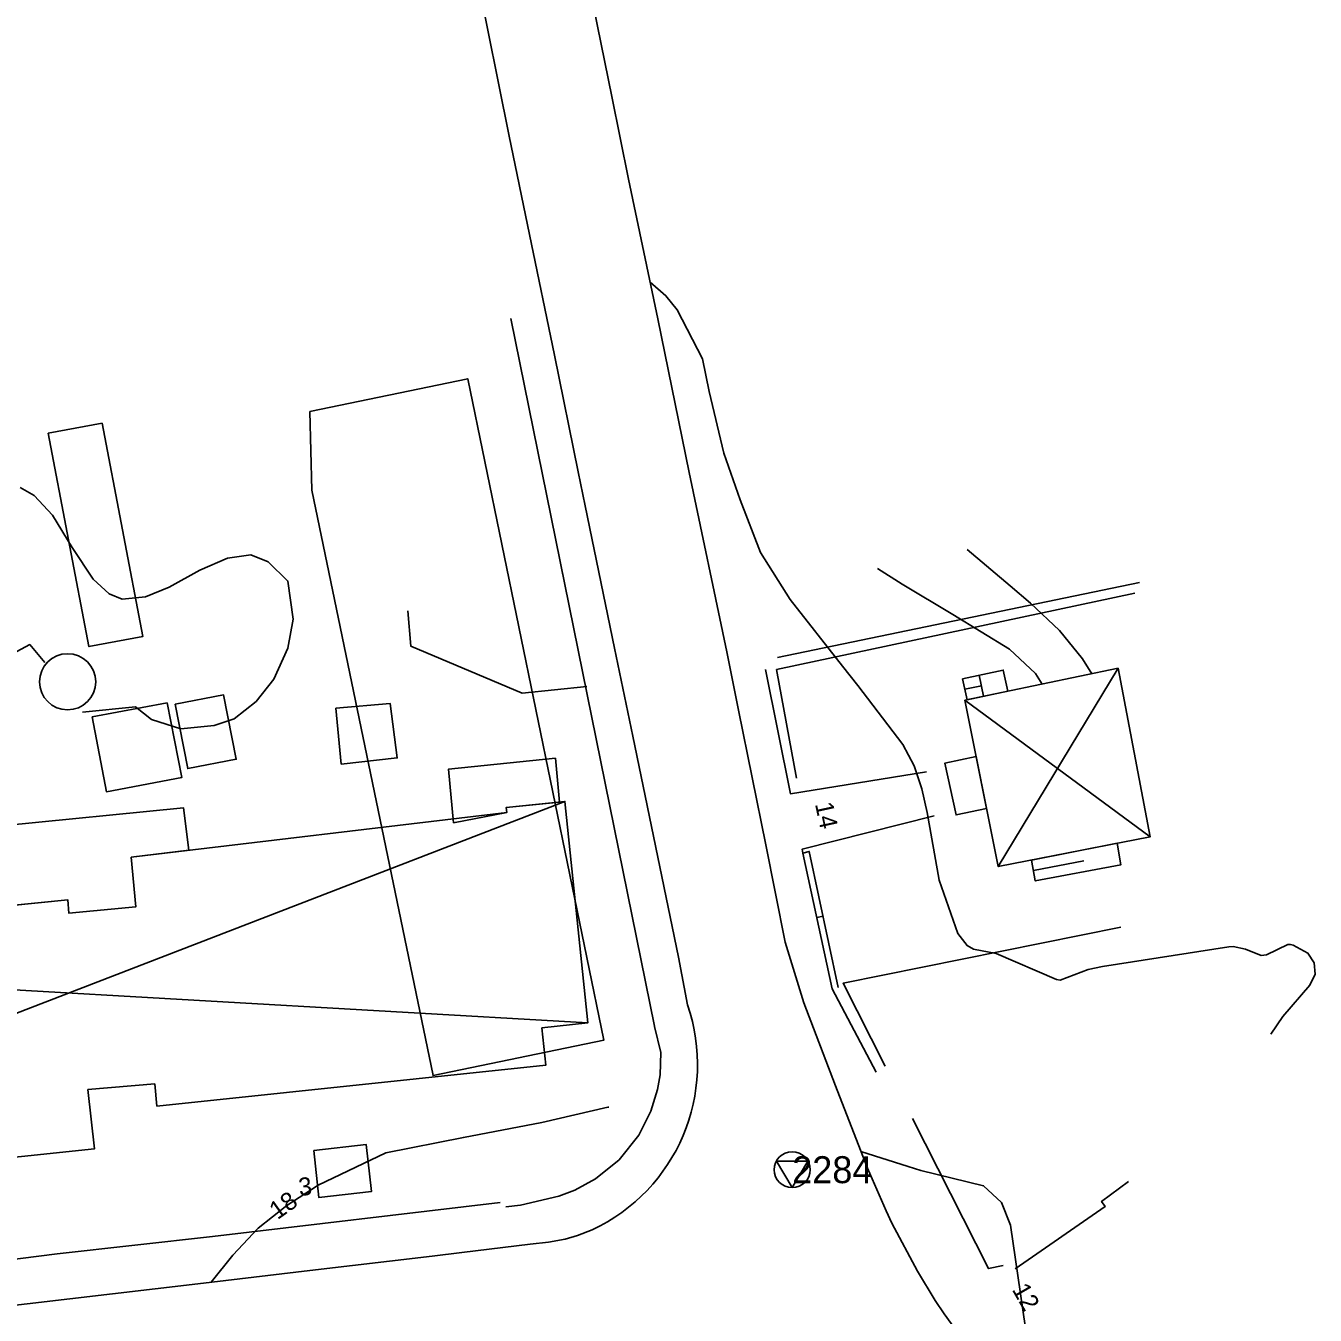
# Model space of a CAD drawing. Extents: x 67169 to 69652, y 20189 to 22818.
# Drawn here: x 69486.1 to 69557.9, y 21241.7 to 21313.4 of the extents above; entities that cross this region are included whole.
import ezdxf

# ---------------------------------------------------------------- set-up
doc = ezdxf.new("R2010")
doc.units = 0
for name, color, linetype in [('BYGGNAD_HUSLIV', 7, 'Continuous'), ('BYGGNAD_HUSLIV 11', 7, 'Continuous'), ('BYGGNAD_HUSLIV 13', 7, 'Continuous'), ('BYGGNADER 263', 7, 'Continuous'), ('BYGGNADSDETALJER', 7, 'Continuous'), ('BYGGNADSSYMBOLER', 7, 'Continuous'), ('BYGGNADSSYMBOLER 30', 7, 'Continuous'), ('HOJDKURVOR_2014', 7, 'Continuous'), ('HOJDKURVOR_2014 5M', 7, 'Continuous'), ('HOJDKURVOR_TEXTER_2014', 7, 'Continuous'), ('Instruktioner', 7, 'Continuous'), ('MUR_STAKET', 7, 'Continuous'), ('MUR_STAKET_SYMBOL', 7, 'Continuous'), ('Std_Ritningsstämpel', 7, 'Continuous'), ('STOMPUNKTER', 7, 'Continuous'), ('STOMPUNKTER TEXT', 7, 'Continuous'), ('VAGAR 121', 7, 'Continuous'), ('VAGAR 123', 7, 'Continuous')]:
    doc.layers.add(name, color=color, linetype=linetype)

msp = doc.modelspace()

# ---------------------------------------------------------------- linework, layer by layer
at = {"layer": 'BYGGNAD_HUSLIV'}
for points in [[(69501.929, 21291.979), (69510.723, 21293.801), (69518.288, 21256.985), (69508.792, 21255.019), (69502.045, 21287.61), (69501.929, 21291.979)], [(69490.379, 21291.325), (69487.382, 21290.767), (69489.637, 21278.898), (69492.633, 21279.455), (69490.379, 21291.325)], [(69538.382, 21275.915), (69546.908, 21277.689), (69548.7, 21268.312), (69540.242, 21266.657), (69538.382, 21275.915)], [(69489.823, 21274.997), (69493.991, 21275.759), (69494.809, 21271.605), (69490.613, 21270.815), (69489.823, 21274.997)], [(69494.431, 21275.692), (69497.13, 21276.212), (69497.839, 21272.627), (69495.14, 21272.107), (69494.431, 21275.692)], [(69502.147, 21250.854), (69505.07, 21251.182), (69505.364, 21248.563), (69502.438, 21248.23), (69502.147, 21250.854)]]:
    msp.add_lwpolyline(points, dxfattribs=at)
at = {"layer": 'BYGGNAD_HUSLIV 11'}
msp.add_lwpolyline([(69538.382, 21275.915), (69546.908, 21277.689), (69548.7, 21268.312), (69540.242, 21266.657), (69538.382, 21275.915)], dxfattribs=at)
at = {"layer": 'BYGGNAD_HUSLIV 13'}
msp.add_lwpolyline([(69501.929, 21291.979), (69510.723, 21293.801), (69518.288, 21256.985), (69508.792, 21255.019), (69502.045, 21287.61), (69501.929, 21291.979)], dxfattribs=at)
at = {"layer": 'BYGGNADER 263'}
msp.add_lwpolyline([(69457.075, 21247.49), (69489.948, 21250.943), (69489.585, 21254.242), (69493.303, 21254.555), (69493.42, 21253.325), (69515.065, 21255.593), (69514.846, 21257.672), (69517.406, 21257.961), (69516.126, 21270.278), (69512.857, 21269.94), (69512.89, 21269.658), (69491.998, 21267.173), (69492.254, 21264.415), (69488.531, 21264.059), (69488.461, 21264.806), (69468.637, 21262.794)], dxfattribs=at)
at = {"layer": 'BYGGNADSDETALJER'}
msp.add_line((69539.185, 21277.301), (69539.416, 21276.13), dxfattribs=at)
for points in [[(69540.771, 21276.412), (69538.511, 21275.941), (69538.255, 21277.099), (69540.518, 21277.59), (69540.771, 21276.412)], [(69539.594, 21269.877), (69539.011, 21272.782), (69537.277, 21272.415), (69537.89, 21269.53), (69539.594, 21269.877)], [(69546.856, 21267.951), (69542.092, 21267.019), (69542.299, 21265.857), (69547.067, 21266.753), (69546.856, 21267.951)]]:
    msp.add_lwpolyline(points, dxfattribs=at)
at = {"layer": 'BYGGNADSSYMBOLER'}
for p, q in [((69546.908, 21277.689), (69540.242, 21266.657)), ((69538.382, 21276.519), (69538.382, 21276.519)), ((69538.383, 21276.52), (69539.3, 21276.716)), ((69538.382, 21275.915), (69548.7, 21268.312)), ((69457.075, 21247.49), (69516.126, 21270.278)), ((69545.005, 21266.976), (69542.195, 21266.438)), ((69455.683, 21261.497), (69517.406, 21257.961))]:
    msp.add_line(p, q, dxfattribs=at)
at = {"layer": 'BYGGNADSSYMBOLER 30'}
for p, q in [((69546.908, 21277.689), (69540.242, 21266.657)), ((69538.382, 21275.915), (69548.7, 21268.312)), ((69457.075, 21247.49), (69516.126, 21270.278)), ((69455.683, 21261.497), (69517.406, 21257.961))]:
    msp.add_line(p, q, dxfattribs=at)
at = {"layer": 'HOJDKURVOR_2014'}
msp.add_line((69518.575, 21253.27), (69518.508, 21253.259), dxfattribs=at)
for points in [[(69555.414, 21257.331), (69556.071, 21258.306), (69557.584, 21260.062), (69557.877, 21260.662), (69557.827, 21261.302), (69557.472, 21261.842), (69556.655, 21262.288), (69556.504, 21262.313), (69556.357, 21262.313), (69555.164, 21261.737), (69554.877, 21261.71), (69553.994, 21262.05), (69553.309, 21262.21), (69553.07, 21262.196), (69546.049, 21261.099), (69545.246, 21260.922), (69543.688, 21260.33), (69543.487, 21260.363), (69540.123, 21261.814), (69538.868, 21262.057), (69538.506, 21262.255), (69537.999, 21262.93), (69536.948, 21265.902), (69536.291, 21269.663), (69535.991, 21270.989), (69535.558, 21272.258), (69534.926, 21273.44), (69532.428, 21276.727), (69531.567, 21277.813), (69528.654, 21281.519), (69527.004, 21284.135), (69525.878, 21287.067), (69524.977, 21289.671), (69524.153, 21293.086), (69523.785, 21294.913), (69522.369, 21297.635), (69521.747, 21298.426), (69520.867, 21299.172)], [(69545.457, 21277.387), (69544.924, 21278.224), (69543.65, 21279.801), (69542.026, 21281.31), (69540.899, 21282.274), (69538.505, 21284.299)], [(69518.508, 21253.259), (69514.842, 21252.418), (69510.478, 21251.578), (69506.158, 21250.713), (69502.396, 21248.931), (69500.661, 21247.796), (69499.054, 21246.52), (69497.641, 21245.032), (69496.444, 21243.516)], [(69541.112, 21237.158), (69541.264, 21238.577), (69541.506, 21239.476), (69541.769, 21240.355), (69541.781, 21240.656), (69541.762, 21240.962), (69540.917, 21246.691), (69540.42, 21247.96), (69539.425, 21248.889), (69535.927, 21249.746), (69535.227, 21249.954), (69532.594, 21250.801)]]:
    msp.add_lwpolyline(points, dxfattribs=at)
at = {"layer": 'HOJDKURVOR_2014 5M'}
msp.add_lwpolyline([(69542.689, 21276.811), (69542.313, 21277.398), (69540.864, 21278.749), (69537.72, 21280.689), (69534.885, 21282.371), (69533.53, 21283.251)], dxfattribs=at)
at = {"layer": 'MUR_STAKET'}
for p, q in [((69527.958, 21278.292), (69548.092, 21282.463)), ((69529.723, 21267.497), (69531.334, 21259.932)), ((69530.489, 21263.896), (69530.143, 21263.816)), ((69533.446, 21255.214), (69530.999, 21259.849))]:
    msp.add_line(p, q, dxfattribs=at)
for points in [[(69512.845, 21247.713), (69513.657, 21247.81), (69515.797, 21248.315), (69516.686, 21248.647), (69517.831, 21249.267), (69519.146, 21250.339), (69520.238, 21251.713), (69520.91, 21253.038), (69521.281, 21254.246), (69521.421, 21255.071), (69521.469, 21256.303), (69521.12, 21257.75), (69521.117, 21257.775), (69513.109, 21297.152)], [(69547.843, 21281.873), (69527.91, 21277.615), (69529.018, 21271.576)], [(69536.246, 21271.925), (69528.682, 21270.695), (69527.28, 21277.618)], [(69538.255, 21277.099), (69540.518, 21277.59), (69540.771, 21276.412), (69540.772, 21276.436)], [(69536.67, 21269.47), (69529.334, 21267.625), (69529.372, 21267.399)], [(69530.999, 21259.849), (69529.372, 21267.399), (69529.723, 21267.497), (69531.334, 21259.932)], [(69533.946, 21255.539), (69531.61, 21260.157), (69547.065, 21263.276)], [(69535.465, 21252.634), (69539.704, 21244.278), (69540.51, 21244.45)], [(69547.497, 21249.12), (69545.992, 21248.018), (69546.198, 21247.741), (69541.177, 21244.258)], [(69453.746, 21245.033), (69459.443, 21241.706), (69479.537, 21244.038), (69487.878, 21245.093), (69496.515, 21246.063), (69512.523, 21247.961)]]:
    msp.add_lwpolyline(points, dxfattribs=at)
at = {"layer": 'MUR_STAKET_SYMBOL'}
for p, q in [((69515.936, 21282.94), (69515.936, 21282.94)), ((69546.754, 21282.186), (69546.754, 21282.186)), ((69548.09, 21282.463), (69548.09, 21282.463)), ((69543.836, 21281.581), (69543.836, 21281.581)), ((69545.287, 21281.882), (69545.287, 21281.882)), ((69540.904, 21280.974), (69540.904, 21280.974)), ((69542.367, 21281.276), (69542.367, 21281.276)), ((69536.423, 21280.045), (69536.423, 21280.045)), ((69537.964, 21280.365), (69537.964, 21280.365)), ((69539.484, 21280.68), (69539.484, 21280.68)), ((69542.241, 21280.676), (69542.241, 21280.676)), ((69533.533, 21279.446), (69533.533, 21279.446)), ((69535.037, 21279.758), (69535.037, 21279.758)), ((69530.596, 21278.838), (69530.596, 21278.838)), ((69532.083, 21279.146), (69532.083, 21279.146)), ((69532.763, 21278.651), (69532.763, 21278.651)), ((69529.181, 21278.545), (69529.181, 21278.545)), ((69539.385, 21277.343), (69539.385, 21277.343)), ((69540.517, 21277.589), (69540.517, 21277.589)), ((69538.254, 21277.098), (69538.254, 21277.098)), ((69540.643, 21277.001), (69540.643, 21277.001)), ((69528.295, 21275.512), (69528.295, 21275.512)), ((69533.344, 21271.452), (69533.344, 21271.452)), ((69534.83, 21271.694), (69534.83, 21271.694)), ((69536.245, 21271.924), (69536.245, 21271.924)), ((69530.373, 21270.968), (69530.373, 21270.968)), ((69531.876, 21271.214), (69531.876, 21271.214)), ((69536.67, 21269.469), (69536.67, 21269.469)), ((69533.75, 21268.734), (69533.75, 21268.734)), ((69535.256, 21269.113), (69535.256, 21269.113)), ((69530.879, 21268.013), (69530.879, 21268.013)), ((69532.299, 21268.37), (69532.299, 21268.37)), ((69519.161, 21267.271), (69519.161, 21267.271)), ((69530.52, 21263.742), (69530.52, 21263.742)), ((69539.404, 21261.728), (69539.404, 21261.728)), ((69531.409, 21259.086), (69531.409, 21259.086)), ((69532.078, 21257.812), (69532.078, 21257.812)), ((69532.907, 21257.587), (69532.907, 21257.587)), ((69532.797, 21256.444), (69532.797, 21256.444)), ((69533.444, 21255.212), (69533.444, 21255.212)), ((69519.544, 21250.842), (69519.544, 21250.842)), ((69536.982, 21249.64), (69536.982, 21249.64)), ((69547.104, 21248.833), (69547.104, 21248.833)), ((69545.99, 21248.016), (69545.99, 21248.016)), ((69506.765, 21247.279), (69506.765, 21247.279)), ((69544.894, 21246.837), (69544.894, 21246.837)), ((69494.889, 21245.88), (69494.889, 21245.88)), ((69543.661, 21245.982), (69543.661, 21245.982)), ((69542.428, 21245.125), (69542.428, 21245.125)), ((69541.177, 21244.258), (69541.177, 21244.258))]:
    msp.add_line(p, q, dxfattribs=at)
at = {"layer": 'Std_Ritningsstämpel'}
for points in [[(69538.382, 21275.915), (69540.242, 21266.657), (69548.7, 21268.312), (69546.908, 21277.689)], [(69509.926, 21269.094), (69512.89, 21269.658), (69512.857, 21269.94), (69515.828, 21270.247), (69515.598, 21272.681), (69509.645, 21272.071)], [(69509.926, 21269.094), (69512.89, 21269.658), (69512.857, 21269.94), (69515.828, 21270.247), (69515.598, 21272.681), (69509.645, 21272.071)], [(69485.317, 21264.487), (69488.461, 21264.806), (69488.531, 21264.059), (69492.254, 21264.415), (69491.998, 21267.173), (69495.202, 21267.57), (69494.899, 21269.93), (69484.797, 21268.919)], [(69485.317, 21264.487), (69488.461, 21264.806), (69488.531, 21264.059), (69492.254, 21264.415), (69491.998, 21267.173), (69495.202, 21267.57), (69494.899, 21269.93), (69484.797, 21268.919)]]:
    msp.add_lwpolyline(points, close=True, dxfattribs=at)
at = {"layer": 'STOMPUNKTER'}
msp.add_lwpolyline([(69528.775, 21248.783), (69529.653, 21250.263), (69527.9, 21250.263)], close=True, dxfattribs=at)
msp.add_circle((69528.775, 21249.783), 1, dxfattribs=at)
at = {"layer": 'VAGAR 121'}
for points in [[(69529.425, 21259.078), (69528.391, 21262.441), (69527.307, 21267.87), (69525.784, 21275.357), (69525.131, 21278.611), (69523.044, 21288.583), (69521.292, 21297.142), (69519.664, 21304.911), (69518.746, 21309.509), (69517.119, 21317.458), (69516.646, 21319.786), (69514.546, 21329.95), (69512.348, 21340.559), (69511.041, 21346.958), (69510.874, 21348.121), (69510.817, 21349.437), (69510.913, 21350.781)], [(69511.232, 21316.262), (69513.032, 21307.298), (69514.162, 21301.832), (69515.557, 21295.119), (69516.863, 21288.633), (69517.252, 21286.735), (69518.893, 21278.809), (69519.899, 21273.905), (69522.44, 21261.62), (69522.946, 21258.963)], [(69517.343, 21276.68), (69513.746, 21276.302), (69507.558, 21278.917), (69507.384, 21280.882)], [(69538.017, 21240.684), (69537.23, 21241.753), (69536.736, 21242.497), (69535.749, 21244.132), (69534.321, 21246.815), (69533.995, 21247.496), (69532.956, 21249.865), (69531.18, 21254.455), (69529.425, 21259.078)], [(69517.65, 21246.438), (69516.827, 21246.128), (69516.145, 21245.921), (69515.207, 21245.745), (69514.19, 21245.633), (69510.393, 21245.169), (69508.74, 21244.977), (69501.924, 21244.178), (69495.697, 21243.426), (69481.445, 21241.761), (69467.893, 21240.145), (69456.771, 21238.801), (69455.834, 21238.768), (69454.642, 21238.863), (69453.419, 21239.1), (69452.846, 21239.323), (69451.877, 21239.719), (69450.955, 21240.147), (69449.909, 21240.852)]]:
    msp.add_lwpolyline(points, dxfattribs=at)
msp.add_arc((69513.342, 21255.642), 10.162, 295.0821, 19.07365, dxfattribs=at)
at = {"layer": 'VAGAR 123'}
for points in [[(69485.821, 21287.744), (69486.601, 21287.303), (69487.617, 21286.208), (69488.707, 21284.404), (69489.87, 21282.657), (69490.762, 21281.842), (69491.482, 21281.54), (69492.781, 21281.673), (69494.113, 21282.2), (69495.813, 21283.155), (69497.349, 21283.825), (69498.642, 21284.002), (69499.617, 21283.613), (69500.711, 21282.545), (69501.01, 21280.432), (69500.7, 21278.816), (69499.923, 21277.076), (69498.94, 21275.839), (69497.728, 21274.88), (69496.612, 21274.5), (69494.76, 21274.32), (69493.116, 21274.836), (69492.236, 21275.539), (69489.279, 21275.243)], [(69487.183, 21278.019), (69486.349, 21279.007), (69485.382, 21278.494)], [(69503.673, 21272.359), (69503.382, 21275.464), (69506.408, 21275.728), (69506.801, 21272.699), (69503.673, 21272.359)]]:
    msp.add_lwpolyline(points, dxfattribs=at)
for start, end in [(90, 270), (270, 90)]:
    msp.add_arc((69488.455, 21276.938), 1.563, start, end, dxfattribs=at)

# ---------------------------------------------------------------- texts
at = {"layer": 'HOJDKURVOR_TEXTER_2014'}
msp.add_text('18', height=1, rotation=35.39487, dxfattribs=at).set_placement((69500.134, 21246.971))
at = {"layer": 'Instruktioner'}
for s, rotation, p in [('14', 282.31678, (69530.038, 21270.134)), ('3', 6.46037, (69501.36, 21248.316)), ('12', 299.84248, (69540.981, 21243.113))]:
    msp.add_text(s, height=1, rotation=rotation, dxfattribs=at).set_placement(p)
at = {"layer": 'STOMPUNKTER TEXT'}
msp.add_text('2284', height=1.5, dxfattribs=at).set_placement((69528.775, 21249.033))

doc.saveas('drawing.dxf')
